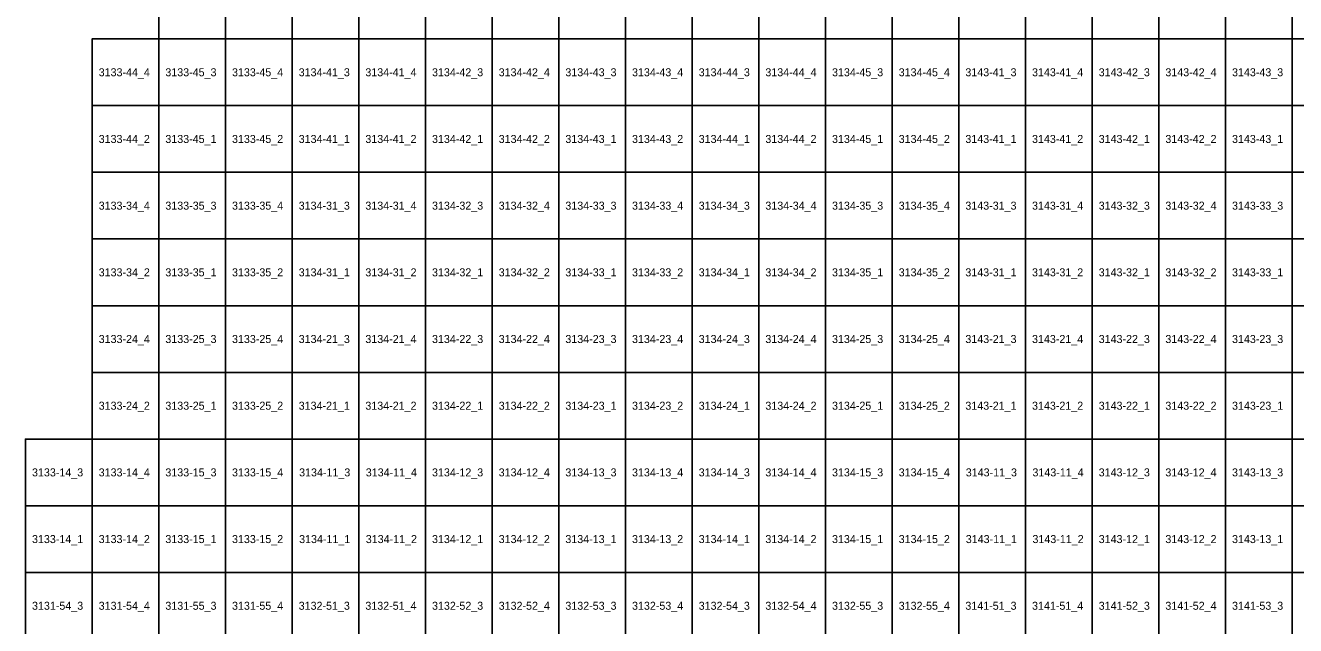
# Model space of a CAD drawing. Extents: x 312500 to 765000, y 172500 to 440000.
# Drawn here: x 315000 to 362632, y 273007 to 295507 of the extents above; entities that cross this region are included whole.
import ezdxf

# ---------------------------------------------------------------- set-up
doc = ezdxf.new("R2010")
doc.units = 0
doc.layers.add('Topo5_ramis_TKS2025', color=7, linetype='Continuous')
doc.layers.add('Topo5_ramis_TKS2025_Nr', color=7, linetype='Continuous')

msp = doc.modelspace()

# ---------------------------------------------------------------- linework, layer by layer
at = {"layer": 'Topo5_ramis_TKS2025'}
for points in [[(320000, 295000), (320000, 297500), (322500, 297500), (322500, 295000), (320000, 295000)], [(322500, 295000), (322500, 297500), (325000, 297500), (325000, 295000), (322500, 295000)], [(325000, 295000), (325000, 297500), (327500, 297500), (327500, 295000), (325000, 295000)], [(327500, 295000), (327500, 297500), (330000, 297500), (330000, 295000), (327500, 295000)], [(330000, 295000), (330000, 297500), (332500, 297500), (332500, 295000), (330000, 295000)], [(332500, 295000), (332500, 297500), (335000, 297500), (335000, 295000), (332500, 295000)], [(335000, 295000), (335000, 297500), (337500, 297500), (337500, 295000), (335000, 295000)], [(337500, 295000), (337500, 297500), (340000, 297500), (340000, 295000), (337500, 295000)], [(340000, 295000), (340000, 297500), (342500, 297500), (342500, 295000), (340000, 295000)], [(342500, 295000), (342500, 297500), (345000, 297500), (345000, 295000), (342500, 295000)], [(345000, 295000), (345000, 297500), (347500, 297500), (347500, 295000), (345000, 295000)], [(347500, 295000), (347500, 297500), (350000, 297500), (350000, 295000), (347500, 295000)], [(350000, 295000), (350000, 297500), (352500, 297500), (352500, 295000), (350000, 295000)], [(352500, 295000), (352500, 297500), (355000, 297500), (355000, 295000), (352500, 295000)], [(355000, 295000), (355000, 297500), (357500, 297500), (357500, 295000), (355000, 295000)], [(357500, 295000), (357500, 297500), (360000, 297500), (360000, 295000), (357500, 295000)], [(360000, 295000), (360000, 297500), (362500, 297500), (362500, 295000), (360000, 295000)], [(362500, 295000), (362500, 297500), (365000, 297500), (365000, 295000), (362500, 295000)], [(317500, 292500), (317500, 295000), (320000, 295000), (320000, 292500), (317500, 292500)], [(320000, 292500), (320000, 295000), (322500, 295000), (322500, 292500), (320000, 292500)], [(322500, 292500), (322500, 295000), (325000, 295000), (325000, 292500), (322500, 292500)], [(325000, 292500), (325000, 295000), (327500, 295000), (327500, 292500), (325000, 292500)], [(327500, 292500), (327500, 295000), (330000, 295000), (330000, 292500), (327500, 292500)], [(330000, 292500), (330000, 295000), (332500, 295000), (332500, 292500), (330000, 292500)], [(332500, 292500), (332500, 295000), (335000, 295000), (335000, 292500), (332500, 292500)], [(335000, 292500), (335000, 295000), (337500, 295000), (337500, 292500), (335000, 292500)], [(337500, 292500), (337500, 295000), (340000, 295000), (340000, 292500), (337500, 292500)], [(340000, 292500), (340000, 295000), (342500, 295000), (342500, 292500), (340000, 292500)], [(342500, 292500), (342500, 295000), (345000, 295000), (345000, 292500), (342500, 292500)], [(345000, 292500), (345000, 295000), (347500, 295000), (347500, 292500), (345000, 292500)], [(347500, 292500), (347500, 295000), (350000, 295000), (350000, 292500), (347500, 292500)], [(350000, 292500), (350000, 295000), (352500, 295000), (352500, 292500), (350000, 292500)], [(352500, 292500), (352500, 295000), (355000, 295000), (355000, 292500), (352500, 292500)], [(355000, 292500), (355000, 295000), (357500, 295000), (357500, 292500), (355000, 292500)], [(357500, 292500), (357500, 295000), (360000, 295000), (360000, 292500), (357500, 292500)], [(360000, 292500), (360000, 295000), (362500, 295000), (362500, 292500), (360000, 292500)], [(362500, 292500), (362500, 295000), (365000, 295000), (365000, 292500), (362500, 292500)], [(317500, 290000), (317500, 292500), (320000, 292500), (320000, 290000), (317500, 290000)], [(320000, 290000), (320000, 292500), (322500, 292500), (322500, 290000), (320000, 290000)], [(322500, 290000), (322500, 292500), (325000, 292500), (325000, 290000), (322500, 290000)], [(325000, 290000), (325000, 292500), (327500, 292500), (327500, 290000), (325000, 290000)], [(327500, 290000), (327500, 292500), (330000, 292500), (330000, 290000), (327500, 290000)], [(330000, 290000), (330000, 292500), (332500, 292500), (332500, 290000), (330000, 290000)], [(332500, 290000), (332500, 292500), (335000, 292500), (335000, 290000), (332500, 290000)], [(335000, 290000), (335000, 292500), (337500, 292500), (337500, 290000), (335000, 290000)], [(337500, 290000), (337500, 292500), (340000, 292500), (340000, 290000), (337500, 290000)], [(340000, 290000), (340000, 292500), (342500, 292500), (342500, 290000), (340000, 290000)], [(342500, 290000), (342500, 292500), (345000, 292500), (345000, 290000), (342500, 290000)], [(345000, 290000), (345000, 292500), (347500, 292500), (347500, 290000), (345000, 290000)], [(347500, 290000), (347500, 292500), (350000, 292500), (350000, 290000), (347500, 290000)], [(350000, 290000), (350000, 292500), (352500, 292500), (352500, 290000), (350000, 290000)], [(352500, 290000), (352500, 292500), (355000, 292500), (355000, 290000), (352500, 290000)], [(355000, 290000), (355000, 292500), (357500, 292500), (357500, 290000), (355000, 290000)], [(357500, 290000), (357500, 292500), (360000, 292500), (360000, 290000), (357500, 290000)], [(360000, 290000), (360000, 292500), (362500, 292500), (362500, 290000), (360000, 290000)], [(362500, 290000), (362500, 292500), (365000, 292500), (365000, 290000), (362500, 290000)], [(317500, 287500), (317500, 290000), (320000, 290000), (320000, 287500), (317500, 287500)], [(320000, 287500), (320000, 290000), (322500, 290000), (322500, 287500), (320000, 287500)], [(322500, 287500), (322500, 290000), (325000, 290000), (325000, 287500), (322500, 287500)], [(325000, 287500), (325000, 290000), (327500, 290000), (327500, 287500), (325000, 287500)], [(327500, 287500), (327500, 290000), (330000, 290000), (330000, 287500), (327500, 287500)], [(330000, 287500), (330000, 290000), (332500, 290000), (332500, 287500), (330000, 287500)], [(332500, 287500), (332500, 290000), (335000, 290000), (335000, 287500), (332500, 287500)], [(335000, 287500), (335000, 290000), (337500, 290000), (337500, 287500), (335000, 287500)], [(337500, 287500), (337500, 290000), (340000, 290000), (340000, 287500), (337500, 287500)], [(340000, 287500), (340000, 290000), (342500, 290000), (342500, 287500), (340000, 287500)], [(342500, 287500), (342500, 290000), (345000, 290000), (345000, 287500), (342500, 287500)], [(345000, 287500), (345000, 290000), (347500, 290000), (347500, 287500), (345000, 287500)], [(347500, 287500), (347500, 290000), (350000, 290000), (350000, 287500), (347500, 287500)], [(350000, 287500), (350000, 290000), (352500, 290000), (352500, 287500), (350000, 287500)], [(352500, 287500), (352500, 290000), (355000, 290000), (355000, 287500), (352500, 287500)], [(355000, 287500), (355000, 290000), (357500, 290000), (357500, 287500), (355000, 287500)], [(357500, 287500), (357500, 290000), (360000, 290000), (360000, 287500), (357500, 287500)], [(360000, 287500), (360000, 290000), (362500, 290000), (362500, 287500), (360000, 287500)], [(362500, 287500), (362500, 290000), (365000, 290000), (365000, 287500), (362500, 287500)], [(317500, 285000), (317500, 287500), (320000, 287500), (320000, 285000), (317500, 285000)], [(320000, 285000), (320000, 287500), (322500, 287500), (322500, 285000), (320000, 285000)], [(322500, 285000), (322500, 287500), (325000, 287500), (325000, 285000), (322500, 285000)], [(325000, 285000), (325000, 287500), (327500, 287500), (327500, 285000), (325000, 285000)], [(327500, 285000), (327500, 287500), (330000, 287500), (330000, 285000), (327500, 285000)], [(330000, 285000), (330000, 287500), (332500, 287500), (332500, 285000), (330000, 285000)], [(332500, 285000), (332500, 287500), (335000, 287500), (335000, 285000), (332500, 285000)], [(335000, 285000), (335000, 287500), (337500, 287500), (337500, 285000), (335000, 285000)], [(337500, 285000), (337500, 287500), (340000, 287500), (340000, 285000), (337500, 285000)], [(340000, 285000), (340000, 287500), (342500, 287500), (342500, 285000), (340000, 285000)], [(342500, 285000), (342500, 287500), (345000, 287500), (345000, 285000), (342500, 285000)], [(345000, 285000), (345000, 287500), (347500, 287500), (347500, 285000), (345000, 285000)], [(347500, 285000), (347500, 287500), (350000, 287500), (350000, 285000), (347500, 285000)], [(350000, 285000), (350000, 287500), (352500, 287500), (352500, 285000), (350000, 285000)], [(352500, 285000), (352500, 287500), (355000, 287500), (355000, 285000), (352500, 285000)], [(355000, 285000), (355000, 287500), (357500, 287500), (357500, 285000), (355000, 285000)], [(357500, 285000), (357500, 287500), (360000, 287500), (360000, 285000), (357500, 285000)], [(360000, 285000), (360000, 287500), (362500, 287500), (362500, 285000), (360000, 285000)], [(362500, 285000), (362500, 287500), (365000, 287500), (365000, 285000), (362500, 285000)], [(317500, 282500), (317500, 285000), (320000, 285000), (320000, 282500), (317500, 282500)], [(320000, 282500), (320000, 285000), (322500, 285000), (322500, 282500), (320000, 282500)], [(322500, 282500), (322500, 285000), (325000, 285000), (325000, 282500), (322500, 282500)], [(325000, 282500), (325000, 285000), (327500, 285000), (327500, 282500), (325000, 282500)], [(327500, 282500), (327500, 285000), (330000, 285000), (330000, 282500), (327500, 282500)], [(330000, 282500), (330000, 285000), (332500, 285000), (332500, 282500), (330000, 282500)], [(332500, 282500), (332500, 285000), (335000, 285000), (335000, 282500), (332500, 282500)], [(335000, 282500), (335000, 285000), (337500, 285000), (337500, 282500), (335000, 282500)], [(337500, 282500), (337500, 285000), (340000, 285000), (340000, 282500), (337500, 282500)], [(340000, 282500), (340000, 285000), (342500, 285000), (342500, 282500), (340000, 282500)], [(342500, 282500), (342500, 285000), (345000, 285000), (345000, 282500), (342500, 282500)], [(345000, 282500), (345000, 285000), (347500, 285000), (347500, 282500), (345000, 282500)], [(347500, 282500), (347500, 285000), (350000, 285000), (350000, 282500), (347500, 282500)], [(350000, 282500), (350000, 285000), (352500, 285000), (352500, 282500), (350000, 282500)], [(352500, 282500), (352500, 285000), (355000, 285000), (355000, 282500), (352500, 282500)], [(355000, 282500), (355000, 285000), (357500, 285000), (357500, 282500), (355000, 282500)], [(357500, 282500), (357500, 285000), (360000, 285000), (360000, 282500), (357500, 282500)], [(360000, 282500), (360000, 285000), (362500, 285000), (362500, 282500), (360000, 282500)], [(362500, 282500), (362500, 285000), (365000, 285000), (365000, 282500), (362500, 282500)], [(317500, 280000), (317500, 282500), (320000, 282500), (320000, 280000), (317500, 280000)], [(320000, 280000), (320000, 282500), (322500, 282500), (322500, 280000), (320000, 280000)], [(322500, 280000), (322500, 282500), (325000, 282500), (325000, 280000), (322500, 280000)], [(325000, 280000), (325000, 282500), (327500, 282500), (327500, 280000), (325000, 280000)], [(327500, 280000), (327500, 282500), (330000, 282500), (330000, 280000), (327500, 280000)], [(330000, 280000), (330000, 282500), (332500, 282500), (332500, 280000), (330000, 280000)], [(332500, 280000), (332500, 282500), (335000, 282500), (335000, 280000), (332500, 280000)], [(335000, 280000), (335000, 282500), (337500, 282500), (337500, 280000), (335000, 280000)], [(337500, 280000), (337500, 282500), (340000, 282500), (340000, 280000), (337500, 280000)], [(340000, 280000), (340000, 282500), (342500, 282500), (342500, 280000), (340000, 280000)], [(342500, 280000), (342500, 282500), (345000, 282500), (345000, 280000), (342500, 280000)], [(345000, 280000), (345000, 282500), (347500, 282500), (347500, 280000), (345000, 280000)], [(347500, 280000), (347500, 282500), (350000, 282500), (350000, 280000), (347500, 280000)], [(350000, 280000), (350000, 282500), (352500, 282500), (352500, 280000), (350000, 280000)], [(352500, 280000), (352500, 282500), (355000, 282500), (355000, 280000), (352500, 280000)], [(355000, 280000), (355000, 282500), (357500, 282500), (357500, 280000), (355000, 280000)], [(357500, 280000), (357500, 282500), (360000, 282500), (360000, 280000), (357500, 280000)], [(360000, 280000), (360000, 282500), (362500, 282500), (362500, 280000), (360000, 280000)], [(362500, 280000), (362500, 282500), (365000, 282500), (365000, 280000), (362500, 280000)], [(315000, 277500), (315000, 280000), (317500, 280000), (317500, 277500), (315000, 277500)], [(317500, 277500), (317500, 280000), (320000, 280000), (320000, 277500), (317500, 277500)], [(320000, 277500), (320000, 280000), (322500, 280000), (322500, 277500), (320000, 277500)], [(322500, 277500), (322500, 280000), (325000, 280000), (325000, 277500), (322500, 277500)], [(325000, 277500), (325000, 280000), (327500, 280000), (327500, 277500), (325000, 277500)], [(327500, 277500), (327500, 280000), (330000, 280000), (330000, 277500), (327500, 277500)], [(330000, 277500), (330000, 280000), (332500, 280000), (332500, 277500), (330000, 277500)], [(332500, 277500), (332500, 280000), (335000, 280000), (335000, 277500), (332500, 277500)], [(335000, 277500), (335000, 280000), (337500, 280000), (337500, 277500), (335000, 277500)], [(337500, 277500), (337500, 280000), (340000, 280000), (340000, 277500), (337500, 277500)], [(340000, 277500), (340000, 280000), (342500, 280000), (342500, 277500), (340000, 277500)], [(342500, 277500), (342500, 280000), (345000, 280000), (345000, 277500), (342500, 277500)], [(345000, 277500), (345000, 280000), (347500, 280000), (347500, 277500), (345000, 277500)], [(347500, 277500), (347500, 280000), (350000, 280000), (350000, 277500), (347500, 277500)], [(350000, 277500), (350000, 280000), (352500, 280000), (352500, 277500), (350000, 277500)], [(352500, 277500), (352500, 280000), (355000, 280000), (355000, 277500), (352500, 277500)], [(355000, 277500), (355000, 280000), (357500, 280000), (357500, 277500), (355000, 277500)], [(357500, 277500), (357500, 280000), (360000, 280000), (360000, 277500), (357500, 277500)], [(360000, 277500), (360000, 280000), (362500, 280000), (362500, 277500), (360000, 277500)], [(362500, 277500), (362500, 280000), (365000, 280000), (365000, 277500), (362500, 277500)], [(315000, 275000), (315000, 277500), (317500, 277500), (317500, 275000), (315000, 275000)], [(317500, 275000), (317500, 277500), (320000, 277500), (320000, 275000), (317500, 275000)], [(320000, 275000), (320000, 277500), (322500, 277500), (322500, 275000), (320000, 275000)], [(322500, 275000), (322500, 277500), (325000, 277500), (325000, 275000), (322500, 275000)], [(325000, 275000), (325000, 277500), (327500, 277500), (327500, 275000), (325000, 275000)], [(327500, 275000), (327500, 277500), (330000, 277500), (330000, 275000), (327500, 275000)], [(330000, 275000), (330000, 277500), (332500, 277500), (332500, 275000), (330000, 275000)], [(332500, 275000), (332500, 277500), (335000, 277500), (335000, 275000), (332500, 275000)], [(335000, 275000), (335000, 277500), (337500, 277500), (337500, 275000), (335000, 275000)], [(337500, 275000), (337500, 277500), (340000, 277500), (340000, 275000), (337500, 275000)], [(340000, 275000), (340000, 277500), (342500, 277500), (342500, 275000), (340000, 275000)], [(342500, 275000), (342500, 277500), (345000, 277500), (345000, 275000), (342500, 275000)], [(345000, 275000), (345000, 277500), (347500, 277500), (347500, 275000), (345000, 275000)], [(347500, 275000), (347500, 277500), (350000, 277500), (350000, 275000), (347500, 275000)], [(350000, 275000), (350000, 277500), (352500, 277500), (352500, 275000), (350000, 275000)], [(352500, 275000), (352500, 277500), (355000, 277500), (355000, 275000), (352500, 275000)], [(355000, 275000), (355000, 277500), (357500, 277500), (357500, 275000), (355000, 275000)], [(357500, 275000), (357500, 277500), (360000, 277500), (360000, 275000), (357500, 275000)], [(360000, 275000), (360000, 277500), (362500, 277500), (362500, 275000), (360000, 275000)], [(362500, 275000), (362500, 277500), (365000, 277500), (365000, 275000), (362500, 275000)], [(315000, 272500), (315000, 275000), (317500, 275000), (317500, 272500), (315000, 272500)], [(317500, 272500), (317500, 275000), (320000, 275000), (320000, 272500), (317500, 272500)], [(320000, 272500), (320000, 275000), (322500, 275000), (322500, 272500), (320000, 272500)], [(322500, 272500), (322500, 275000), (325000, 275000), (325000, 272500), (322500, 272500)], [(325000, 272500), (325000, 275000), (327500, 275000), (327500, 272500), (325000, 272500)], [(327500, 272500), (327500, 275000), (330000, 275000), (330000, 272500), (327500, 272500)], [(330000, 272500), (330000, 275000), (332500, 275000), (332500, 272500), (330000, 272500)], [(332500, 272500), (332500, 275000), (335000, 275000), (335000, 272500), (332500, 272500)], [(335000, 272500), (335000, 275000), (337500, 275000), (337500, 272500), (335000, 272500)], [(337500, 272500), (337500, 275000), (340000, 275000), (340000, 272500), (337500, 272500)], [(340000, 272500), (340000, 275000), (342500, 275000), (342500, 272500), (340000, 272500)], [(342500, 272500), (342500, 275000), (345000, 275000), (345000, 272500), (342500, 272500)], [(345000, 272500), (345000, 275000), (347500, 275000), (347500, 272500), (345000, 272500)], [(347500, 272500), (347500, 275000), (350000, 275000), (350000, 272500), (347500, 272500)], [(350000, 272500), (350000, 275000), (352500, 275000), (352500, 272500), (350000, 272500)], [(352500, 272500), (352500, 275000), (355000, 275000), (355000, 272500), (352500, 272500)], [(355000, 272500), (355000, 275000), (357500, 275000), (357500, 272500), (355000, 272500)], [(357500, 272500), (357500, 275000), (360000, 275000), (360000, 272500), (357500, 272500)], [(360000, 272500), (360000, 275000), (362500, 275000), (362500, 272500), (360000, 272500)], [(362500, 272500), (362500, 275000), (365000, 275000), (365000, 272500), (362500, 272500)]]:
    msp.add_lwpolyline(points, dxfattribs=at)

# ---------------------------------------------------------------- texts
at = {"layer": 'Topo5_ramis_TKS2025_Nr'}
for s, p in [('3133-44_4', (317748, 293600)), ('3133-45_3', (320248, 293600)), ('3133-45_4', (322748, 293600)), ('3134-41_3', (325248, 293600)), ('3134-41_4', (327748, 293600)), ('3134-42_3', (330248, 293600)), ('3134-42_4', (332748, 293600)), ('3134-43_3', (335248, 293600)), ('3134-43_4', (337748, 293600)), ('3134-44_3', (340248, 293600)), ('3134-44_4', (342748, 293600)), ('3134-45_3', (345248, 293600)), ('3134-45_4', (347748, 293600)), ('3143-41_3', (350248, 293600)), ('3143-41_4', (352748, 293600)), ('3143-42_3', (355248, 293600)), ('3143-42_4', (357748, 293600)), ('3143-43_3', (360248, 293600)), ('3133-44_2', (317748, 291100)), ('3133-45_1', (320248, 291100)), ('3133-45_2', (322748, 291100)), ('3134-41_1', (325248, 291100)), ('3134-41_2', (327748, 291100)), ('3134-42_1', (330248, 291100)), ('3134-42_2', (332748, 291100)), ('3134-43_1', (335248, 291100)), ('3134-43_2', (337748, 291100)), ('3134-44_1', (340248, 291100)), ('3134-44_2', (342748, 291100)), ('3134-45_1', (345248, 291100)), ('3134-45_2', (347748, 291100)), ('3143-41_1', (350248, 291100)), ('3143-41_2', (352748, 291100)), ('3143-42_1', (355248, 291100)), ('3143-42_2', (357748, 291100)), ('3143-43_1', (360248, 291100)), ('3133-34_4', (317748, 288600)), ('3133-35_3', (320248, 288600)), ('3133-35_4', (322748, 288600)), ('3134-31_3', (325248, 288600)), ('3134-31_4', (327748, 288600)), ('3134-32_3', (330248, 288600)), ('3134-32_4', (332748, 288600)), ('3134-33_3', (335248, 288600)), ('3134-33_4', (337748, 288600)), ('3134-34_3', (340248, 288600)), ('3134-34_4', (342748, 288600)), ('3134-35_3', (345248, 288600)), ('3134-35_4', (347748, 288600)), ('3143-31_3', (350248, 288600)), ('3143-31_4', (352748, 288600)), ('3143-32_3', (355248, 288600)), ('3143-32_4', (357748, 288600)), ('3143-33_3', (360248, 288600)), ('3133-34_2', (317748, 286100)), ('3133-35_1', (320248, 286100)), ('3133-35_2', (322748, 286100)), ('3134-31_1', (325248, 286100)), ('3134-31_2', (327748, 286100)), ('3134-32_1', (330248, 286100)), ('3134-32_2', (332748, 286100)), ('3134-33_1', (335248, 286100)), ('3134-33_2', (337748, 286100)), ('3134-34_1', (340248, 286100)), ('3134-34_2', (342748, 286100)), ('3134-35_1', (345248, 286100)), ('3134-35_2', (347748, 286100)), ('3143-31_1', (350248, 286100)), ('3143-31_2', (352748, 286100)), ('3143-32_1', (355248, 286100)), ('3143-32_2', (357748, 286100)), ('3143-33_1', (360248, 286100)), ('3133-24_4', (317748, 283600)), ('3133-25_3', (320248, 283600)), ('3133-25_4', (322748, 283600)), ('3134-21_3', (325248, 283600)), ('3134-21_4', (327748, 283600)), ('3134-22_3', (330248, 283600)), ('3134-22_4', (332748, 283600)), ('3134-23_3', (335248, 283600)), ('3134-23_4', (337748, 283600)), ('3134-24_3', (340248, 283600)), ('3134-24_4', (342748, 283600)), ('3134-25_3', (345248, 283600)), ('3134-25_4', (347748, 283600)), ('3143-21_3', (350248, 283600)), ('3143-21_4', (352748, 283600)), ('3143-22_3', (355248, 283600)), ('3143-22_4', (357748, 283600)), ('3143-23_3', (360248, 283600)), ('3133-24_2', (317748, 281100)), ('3133-25_1', (320248, 281100)), ('3133-25_2', (322748, 281100)), ('3134-21_1', (325248, 281100)), ('3134-21_2', (327748, 281100)), ('3134-22_1', (330248, 281100)), ('3134-22_2', (332748, 281100)), ('3134-23_1', (335248, 281100)), ('3134-23_2', (337748, 281100)), ('3134-24_1', (340248, 281100)), ('3134-24_2', (342748, 281100)), ('3134-25_1', (345248, 281100)), ('3134-25_2', (347748, 281100)), ('3143-21_1', (350248, 281100)), ('3143-21_2', (352748, 281100)), ('3143-22_1', (355248, 281100)), ('3143-22_2', (357748, 281100)), ('3143-23_1', (360248, 281100)), ('3133-14_3', (315248, 278600)), ('3133-14_4', (317748, 278600)), ('3133-15_3', (320248, 278600)), ('3133-15_4', (322748, 278600)), ('3134-11_3', (325264, 278600)), ('3134-11_4', (327764, 278600)), ('3134-12_3', (330248, 278600)), ('3134-12_4', (332748, 278600)), ('3134-13_3', (335248, 278600)), ('3134-13_4', (337748, 278600)), ('3134-14_3', (340248, 278600)), ('3134-14_4', (342748, 278600)), ('3134-15_3', (345248, 278600)), ('3134-15_4', (347748, 278600)), ('3143-11_3', (350264, 278600)), ('3143-11_4', (352764, 278600)), ('3143-12_3', (355248, 278600)), ('3143-12_4', (357748, 278600)), ('3143-13_3', (360248, 278600)), ('3133-14_1', (315248, 276100)), ('3133-14_2', (317748, 276100)), ('3133-15_1', (320248, 276100)), ('3133-15_2', (322748, 276100)), ('3134-11_1', (325264, 276100)), ('3134-11_2', (327764, 276100)), ('3134-12_1', (330248, 276100)), ('3134-12_2', (332748, 276100)), ('3134-13_1', (335248, 276100)), ('3134-13_2', (337748, 276100)), ('3134-14_1', (340248, 276100)), ('3134-14_2', (342748, 276100)), ('3134-15_1', (345248, 276100)), ('3134-15_2', (347748, 276100)), ('3143-11_1', (350264, 276100)), ('3143-11_2', (352764, 276100)), ('3143-12_1', (355248, 276100)), ('3143-12_2', (357748, 276100)), ('3143-13_1', (360248, 276100)), ('3131-54_3', (315248, 273600)), ('3131-54_4', (317748, 273600)), ('3131-55_3', (320248, 273600)), ('3131-55_4', (322748, 273600)), ('3132-51_3', (325248, 273600)), ('3132-51_4', (327748, 273600)), ('3132-52_3', (330248, 273600)), ('3132-52_4', (332748, 273600)), ('3132-53_3', (335248, 273600)), ('3132-53_4', (337748, 273600)), ('3132-54_3', (340248, 273600)), ('3132-54_4', (342748, 273600)), ('3132-55_3', (345248, 273600)), ('3132-55_4', (347748, 273600)), ('3141-51_3', (350248, 273600)), ('3141-51_4', (352748, 273600)), ('3141-52_3', (355248, 273600)), ('3141-52_4', (357748, 273600)), ('3141-53_3', (360248, 273600))]:
    msp.add_text(s, height=300, dxfattribs=at).set_placement(p)

doc.saveas('drawing.dxf')
